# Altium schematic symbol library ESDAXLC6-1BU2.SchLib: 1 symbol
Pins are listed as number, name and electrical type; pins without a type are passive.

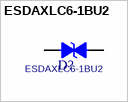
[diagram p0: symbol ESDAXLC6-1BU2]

## ESDAXLC6-1BU2
designator D?
footprint ST_0201B
pins: 1, 2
